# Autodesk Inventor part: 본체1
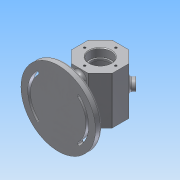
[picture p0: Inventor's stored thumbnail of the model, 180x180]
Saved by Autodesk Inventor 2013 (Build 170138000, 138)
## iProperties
Created: 2017-06
Part Number: 본체1
Material: 알루미늄 6061
Document SubType Name: Modeling
Designer: Administrator
Density: 2.71 g/cm^3
Mass: 562.528 g
Surface Area: 565.55 cm^2
Volume: 207.575 cm^3
Author: Administrator
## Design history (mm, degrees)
sketch "스케치1" dims "d0" = 60
  geometry: L1 (12.426, 30)-(30, 12.426); L2 (30, 12.426)-(30, -12.426); L3 (30, -12.426)-(12.426, -30); L4 (12.426, -30)-(-12.426, -30); L5 (-12.426, -30)-(-30, -12.426); L6 (-30, -12.426)-(-30, 12.426); L7 (-30, 12.426)-(-12.426, 30); L8 (-12.426, 30)-(12.426, 30); L9 (12.426, 30)-(-12.426, -30); L10 (-30, 12.426)-(30, -12.426); 6 further points
  constraints: 20 end point, 3 midpoint, 2 coincident, 1 horizontal alignment, 1 perpendicular, 1 vertical alignment, 19 other
  dimensions: "d1" = 60 distance between parallel lines of L4 L8 (derived); "d2" = 64.94353 distance of L4.end L1.start (derived)
extrude "돌출1" new body sketch "스케치1" stored distance "d3" = 70; taper "d4" = 0 deg
sketch "스케치2"
  geometry: L1 (0, 35)-(0, -35); L2 (30, -35)-(-30, -35) reference; L3 (-30, -35)-(-30, 35) reference; L4 (-30, 35)-(30, 35) reference; L5 (30, 35)-(30, -35) reference; L6 (0, 35)-(16, 35); L7 (16, 35)-(16, 23); L8 (16, 23)-(14, 23); L9 (14, 23)-(14, 20); L10 (14, 20)-(25, 20); L11 (14, -20)-(14, -23); L12 (14, -23)-(16, -23); L13 (16, -23)-(16, -35); L14 (16, -35)-(0, -35); L15 (14, -20)-(25, -20); L16 (25, 20)-(25, -20); 2 further points
  constraints: 24 end point, 5 parallel, 4 collinear, 3 perpendicular, 2 point on line, 1 coincident, 1 midpoint, 1 vertical
  dimensions: "d7" = 32 diameter of L7 L1; "d9" = 32 diameter of L13 L1 (derived); "d11" = 50 diameter of L16 L1; "d12" = 28 diameter of L9 L1; "d13" = 28 diameter of L11 L1; "d14" = 12 distance of L6.end L7.end; "d15" = 40 distance of L10.end L15.end
revolve "회전1" sketch "스케치2" stored, may be unused: angle "d16" = 90 deg
sketch "스케치3" dims "d17" = 46
  geometry: C1 r 16 at (0, 0) reference; 2 further points
  constraints: 2 vertical alignment, 1 coincident, 2 other
hole "구멍1" sketch "스케치3" at (0, 23) diameter "d18" = 3.242; stored, may be unused: countersink angle "d22" = 90 deg, drill point angle "d24" = 118 deg; dims "d19" = 8, "d20" = 4, "d21" = 2, "d23" = 10
node "작업 평면1"
sketch "스케치4"
  geometry: C1 r 55 at (0, 0); 1 further point
  constraints: 1 centre point, 1 coincident
  dimensions: "d29" = 110 diameter of C1
extrude "돌출2" join sketch "스케치4" distance "d30" = 10; taper "d31" = 0 deg
sketch "스케치6"
  geometry: L1 (0, 0)-(48, 0); L2 (0, 0)-(48, 0); L3 (0, 0)-(50, 0); L4 (0, 0)-(50, 0); L5 (0, 0)-(30.406, 30.406); L6 (0, 0)-(30.406, -30.406); C1 r 55 at (0, 0) reference; A1 r 48 centre (0, 0) between (33.941, -33.941) and (33.941, 33.941); A2 r 38 centre (0, 0) between (26.87, -26.87) and (26.87, 26.87); A3 r 43 centre (0, 0) between (30.406, -30.406) and (30.406, 30.406); A4 r 5 centre (30.406, 30.406) between (33.941, 33.941) and (26.87, 26.87); A5 r 5 centre (30.406, -30.406) between (26.87, -26.87) and (33.941, -33.941); A6 r 2 centre (30.406, 30.406) between (31.82, 31.82) and (28.991, 28.991); A7 r 45 centre (0, 0) between (31.82, -31.82) and (31.82, 31.82); A8 r 2 centre (30.406, -30.406) between (28.991, -28.991) and (31.82, -31.82); A9 r 41 centre (0, 0) between (28.991, -28.991) and (28.991, 28.991)
  constraints: 18 point on circle, 12 end point, 9 centre point, 6 coincident, 4 horizontal, 1 perpendicular, 3 other
  dimensions: "d42" = 96 diameter of A1; "d43" = 76 diameter of A2; "d44" = 86 diameter of A3; "d59" = 45 deg angle of L1 L5; "d60" = 10 diameter of A4; "d61" = 10 diameter of A5; "d62" = 3 radial gap between concentric circles of A1 A7; "d63" = 5 radius of A4 (derived); "d64" = 2 radius of A6 (derived)
extrude "돌출3" cut sketch "스케치6" distance "d65" = 3; taper "d66" = 0 deg
extrude "돌출4" cut sketch "스케치6" stored distance "d67" = 3; taper "d68" = 0 deg
sketch "스케치7"
  geometry: L1 (5, 24)-(-5, 24); L2 (-5, 24)-(-5, -24); L3 (-5, -24)-(5, -24); L4 (5, -24)-(5, 24); L5 (5, 24)-(-5, -24); L6 (-5, 24)-(5, -24); L7 (0, 24)-(0, -24); A1 r 38 centre (0, 0) between (26.87, -26.87) and (26.87, 26.87) reference; A2 r 5 centre (0, 24) between (5, 24) and (-5, 24); A3 r 5 centre (0, -24) between (-5, -24) and (5, -24)
  constraints: 14 end point, 4 midpoint, 4 point on circle, 2 centre point, 2 parallel, 2 perpendicular, 1 horizontal
  dimensions: "d72" = 10 distance of L3.end L2.end; "d73" = 48 distance of L1.end L2.end
extrude "돌출5" join sketch "스케치7" stored distance "d74" = 3; taper "d75" = 0 deg
sketch "스케치8"
  geometry: L1 (-48, -52)-(-48, -55) reference; L2 (-48, -55)-(-45, -55) reference; L3 (-45, -55)-(-45, -62) reference; L4 (-45, -62)-(-55, -62) reference; L5 (-55, -62)-(-55, -52) reference; L6 (-55, -52)-(-48, -52) reference; L7 (38, -52)-(38, -55) reference; L8 (38, -55)-(41, -55) reference; L9 (41, -55)-(41, -62) reference; L10 (41, -62)-(-41, -62) reference; L11 (-41, -62)-(-41, -55) reference; L12 (-41, -55)-(-38, -55) reference; L13 (-38, -55)-(-38, -52) reference; L14 (-38, -52)-(-5, -52) reference; L15 (-5, -52)-(-5, -30) reference; L16 (-5, -30)-(-12.426, -30) reference; L17 (-12.426, -30)-(-30, -12.426) reference; L18 (-30, -12.426)-(-30, 12.426) reference; L19 (-30, 12.426)-(-12.426, 30) reference; L20 (-12.426, 30)-(12.426, 30) reference; L21 (12.426, 30)-(30, 12.426) reference; L22 (30, 12.426)-(30, -12.426) reference; L23 (30, -12.426)-(12.426, -30) reference; L24 (12.426, -30)-(5, -30) reference; L25 (5, -30)-(5, -52) reference; L26 (5, -52)-(38, -52) reference; L27 (48, -55)-(48, -52) reference; L28 (48, -52)-(55, -52) reference; L29 (55, -52)-(55, -62) reference; L30 (55, -62)-(45, -62) reference; L31 (45, -62)-(45, -55) reference; L32 (45, -55)-(48, -55) reference; L33 (0, 0)-(21.213, 21.213); L34 (0, 0)-(30, 0); C1 r 25 at (0, 0) reference; 1 further point
  constraints: 4 end point, 1 equal length, 1 horizontal, 1 midpoint
  dimensions: "d76" = 45 deg angle of L34 L33
  node "절단 모서리 투영2"
node "작업 평면4"
sketch "스케치9"
  geometry: C1 r 8 at (0, 0); 1 further point
  constraints: 1 centre point, 1 coincident
  dimensions: "d83" = 16 diameter of C1
extrude "돌출6" join sketch "스케치9" distance "d84" = 7; taper "d85" = 0 deg
hole "구멍2" diameter "d88" = 8; stored, may be unused: countersink angle "d92" = 90 deg, drill point angle "d94" = 0 deg; dims "d86" = 10, "d87" = 10, "d89" = 8, "d90" = 4, "d91" = 2, "d93" = 10
chamfer "모따기1" distance "d95" = 1; stored, may be unused: second distance "d96" = 2, angle "d97" = 45 deg
sketch "스케치10"
  geometry: 1 further point
fillet "모깎기1" dims "d98" = 0.3
fillet "모깎기2" dims "d99" = 3
sketch "스케치11"
  geometry: L1 (24.853, 0)-(0, 0) reference; 2 further points
  constraints: 1 coincident, 1 other
  dimensions: "d101" = 35 distance from line of point (12.426, 35) L1 (derived)
feature "엠보싱1" sketch "스케치11" dims "d102" = 0.5, "d103" = 0
fillet "모깎기3" dims "d104" = 1
fillet "모깎기4" dims "d105" = 3
fillet "모깎기5" dims "d106" = 5
node "솔리드1"
pattern_circular "원형 패턴1" dims angle "d26" = 360 deg
mirror "대칭1"
pattern_circular "원형 패턴2" dims angle "d70" = 360 deg
node "절단 모서리 투영1"
other parameters: "d28" = -62, "d77" = 0, "d78" = 0, "d79" = 0, "d80" = 0, "d81" = 0, "d82" = 0
